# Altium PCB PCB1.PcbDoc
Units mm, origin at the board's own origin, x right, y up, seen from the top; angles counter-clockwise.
Board outline 66.42 x 67.44 mm, 2 copper layers (Top Layer, Bottom Layer); 8 components, 7 nets, 62 pads, 4 vias.
Unrouted connection lines stored in the file: 3.
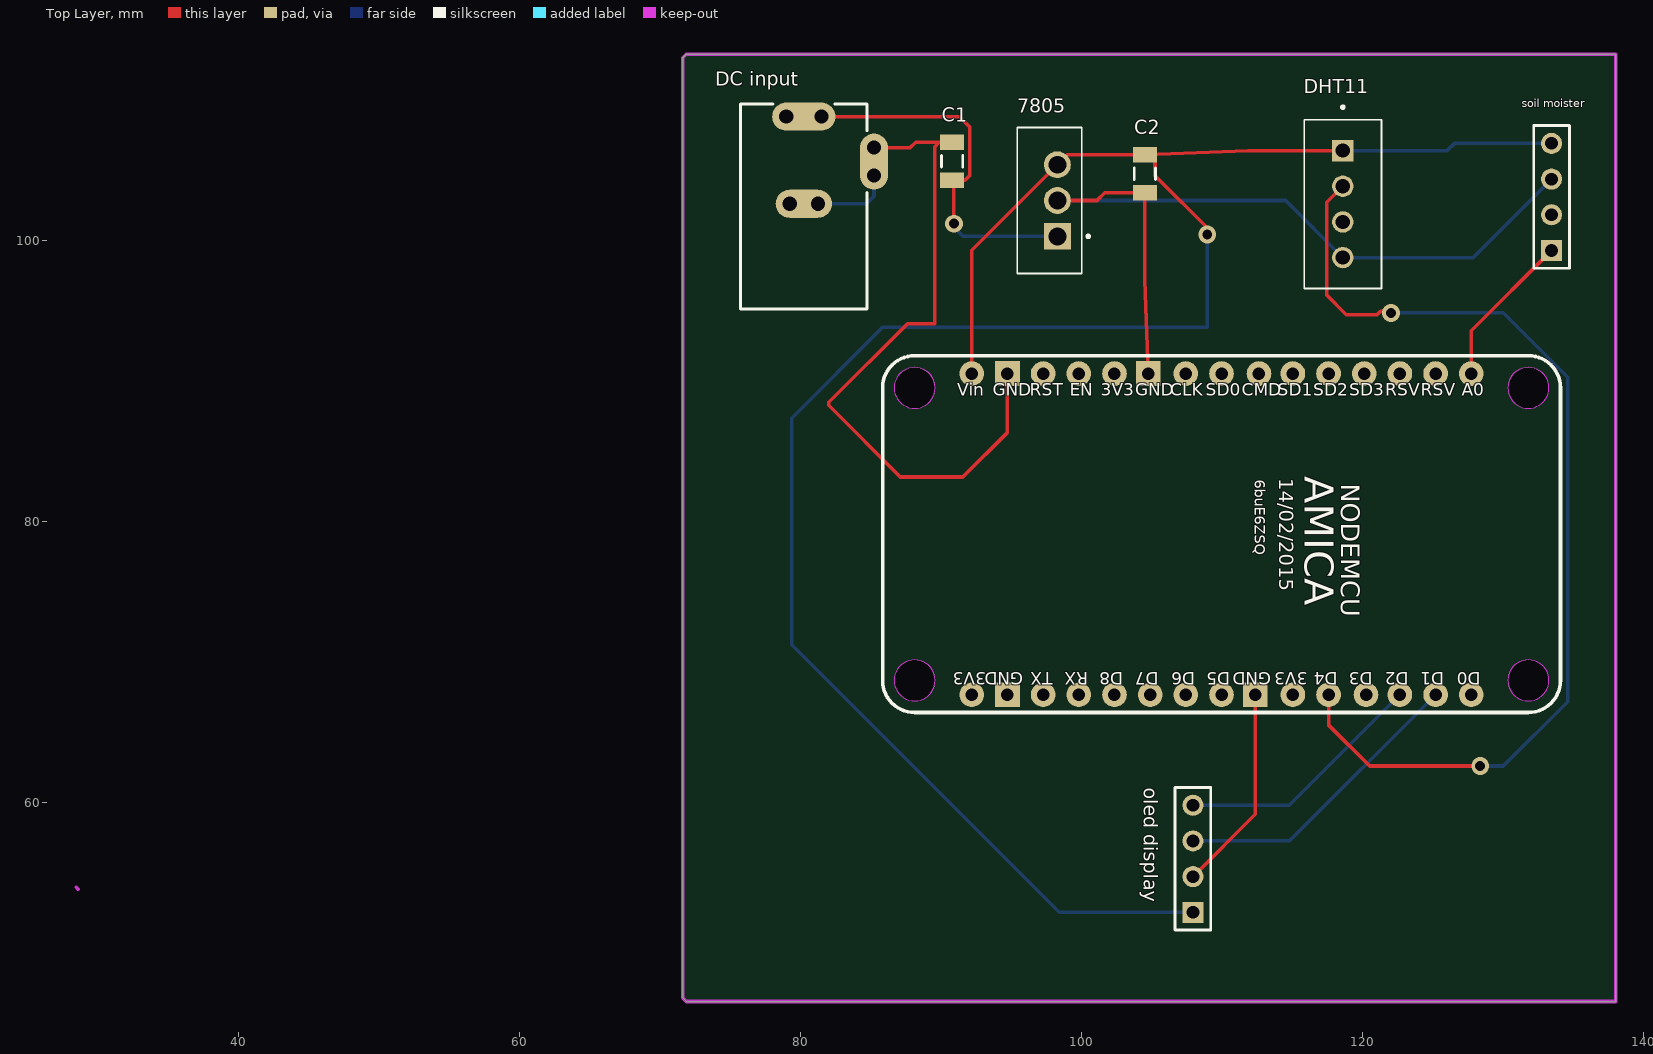
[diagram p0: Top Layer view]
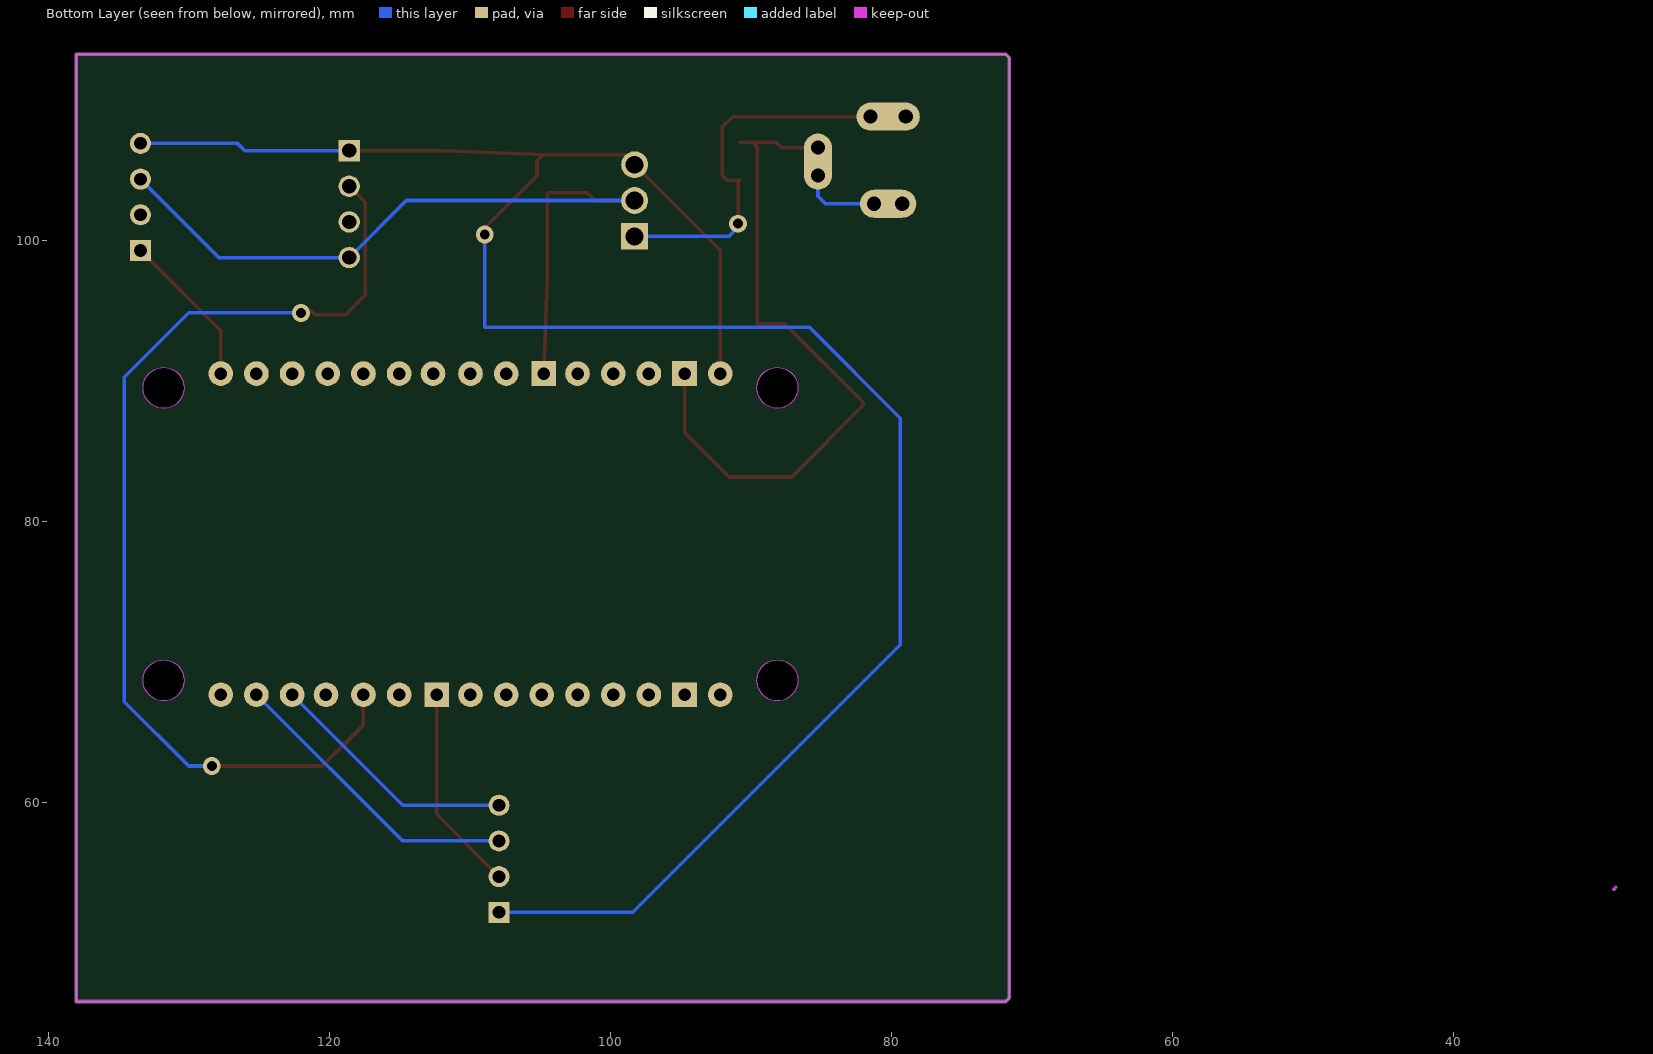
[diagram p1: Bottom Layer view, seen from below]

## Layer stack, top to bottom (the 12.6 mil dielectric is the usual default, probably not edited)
Top Solder: solder mask 0.0102, Solder Resist, Dk 3.5
Top Layer: signal copper 0.0356
Dielectric 1: dielectric 0.32, FR-4, Dk 4.8
Bottom Layer: signal copper 0.0356
Bottom Solder: solder mask 0.0102, Solder Resist, Dk 3.5

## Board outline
71.628,46.101 71.882,45.847 138.049,45.847 138.049,113.284 71.882,113.284 71.628,113.03

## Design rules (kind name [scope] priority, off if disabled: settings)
Clearance [All] p1: gap=0.254 ignorepadtopadclearanceinfootprint=FALSE except(0: Arc-Hole Track-Hole SMDPad-Hole THPad-Hole Via-Hole Fill-Hole Poly-Hole Region-Hole Text-Hole)
PolygonConnect [All] p1: connectstyle=Relief reliefconductorwidth=0.254 reliefentries=4 polygonreliefangle="90 Angle" airgapwidth=0.254
RoutingVias [All] p1: holewidth=0.711 width=1.27 viastyle="Through Hole" minholewidth=0.711 minwidth=1.27 maxholewidth=0.711 maxwidth=1.27
SolderMaskExpansion [All] p1: expansion=0.102 istentingtop=FALSE
Width [All] p1: maxlimit=0.254 minlimit=0.254 preferedwidth=0.254
30 further rules are at their usual default settings.

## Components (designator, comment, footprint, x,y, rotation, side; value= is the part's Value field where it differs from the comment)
7805 "L7805CV" TO255P1040X460X1968-3 98.298,100.32 r90 top
C1 "" C1206 90.805,105.664 r270 top value=10u
C2 "" C1206 104.521,104.775 r90 top value=0.1u
"DC input" "PWR2.5" KLD-0202 80.244,95.139 r90 top
DHT11 "ADA386" XDCR_ADA386 118.618,102.616 r270 top
NodeMCU-? "NodeMCU V1.0 ESP-12E" "NodeMCU V1.0 ESP-12E" 134.01,91.846 r270 top
"oled display" "" HDR1X4 107.95,52.197 r90 top
"soil moister" "" HDR1X4 133.477,99.314 r90 top

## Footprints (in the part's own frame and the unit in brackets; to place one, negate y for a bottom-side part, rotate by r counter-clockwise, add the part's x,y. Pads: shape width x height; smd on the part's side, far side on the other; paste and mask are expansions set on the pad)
C1206 [mm] "Chip Capacitor, Body 3.2x1.6mm, IPC High Density"
  rect 1.1x1.7 smd: 1(-1.35,0) 2(1.35,0)
  silkscreen extent -0.4,-0.75 0.4,0.75, body extent -1.7,-0.9 1.7,0.9, height 1.3
HDR1X4 [mm] "Connector; Header; 4 Position"
  rect 1.5x1.5 hole 0.9: 1(0,0)
  round 1.5 hole 0.9: 2(2.54,0) 3(5.08,0) 4(7.62,0)
  silkscreen extent -1.27,-1.27 8.89,1.27
KLD-0202 [mm] "DC Power Jack, 2.5mm, KLD Series, PCB Mount"
  oval 2x4.5 all layers, no hole: 1(13.7,0)
  round 1.5 hole 1: 1A(13.7,-1.25) 1B(13.7,1.25) 2A(7.5,-1) 2B(7.5,1) 3A(9.5,-5) 3B(11.5,-5)
  oval 2x4 all layers, no hole: 2(7.5,0)
  oval 4x2 all layers, no hole: 3(10.5,-5)
  silkscreen extent 0,-4.5 14.6,4.5
"NodeMCU V1.0 ESP-12E" [mil]
  round 115 hole 115 unplated paste-300 mask-300: 0(91,-86) 0(91,-1806) 0(911,-86) 0(911,-1806)
  round 69 hole 35: 3V3(51,-1246) 3V3(951,-746) 3V3(951,-1646) A0(51,-246) CLK(51,-1046) CMD(51,-841) D0(951,-246) D1(951,-346) D2(951,-446) D3(951,-541) D4(951,-646) D5(951,-946) D6(951,-1046) D7(951,-1146) D8(951,-1246) EN(51,-1346) RST(51,-1446) RSV(51,-346) RSV(51,-446) RX(951,-1346) SD0(51,-946) SD1(51,-746) SD2(51,-646) SD3(51,-546) TX(951,-1446) VIN(51,-1646)
  rect 69x69 hole 35: GND(51,-1151) GND(51,-1546) GND(951,-851) GND(951,-1546)
  Keep-Out Layer circle w2: c911,-1806 r57.5
  Keep-Out Layer circle w2: c91,-1806 r57.5
  Keep-Out Layer circle w2: c911,-86 r57.5
  Keep-Out Layer circle w2: c91,-86 r57.5
  silkscreen extent 1,-1896 1001,4
TO255P1040X460X1968-3 [mm]
  rect 1.91x1.91 hole 1.27: 1(0,0)
  round 1.91 hole 1.27: 2(2.55,0) 3(5.1,0)
  silkscreen extent -2.65,-2.29 7.75,2.86
XDCR_ADA386 [mil]
  rect 60x60 hole 40: 1(-150,0)
  round 60 hole 40: 2(-50,0) 3(50,0) 4(150,0)
  silkscreen extent -276,-108 236,108

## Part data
7805: "Linear Voltage Regulator IC 1 Output 1.5A TO-220AB", Package="TO-220 STMicroelectronics"
C1 C2: library part "Cap Semi", "Capacitor (Semiconductor SIM Model)"
"DC input": "Low Voltage Power Supply Connector"
DHT11: Package=None
NodeMCU-?: "NodeMCU V1.0 ESP8266 (ESP-12E)"
"oled display": library part "Header 4"
"soil moister": library part "Header 4", "soil moister pin header"

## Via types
v1: diameter 1.27, hole 0.711, Top Layer to Bottom Layer, 4 vias

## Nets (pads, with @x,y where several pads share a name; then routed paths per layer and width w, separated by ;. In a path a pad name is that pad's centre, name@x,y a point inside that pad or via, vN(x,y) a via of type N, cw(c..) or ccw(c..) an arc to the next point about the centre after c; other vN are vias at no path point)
A0: "soil moister.1" NodeMCU-?.A0 | length 11.1
  Top Layer w0.254: NodeMCU-?.A0 127.762,93.599 133.477,99.314
DATA: DHT11.2 NodeMCU-?.D4 | length 73.4
  Top Layer w0.254: NodeMCU-?.D4 117.602,65.532 120.523,62.611 v1(128.397,62.611) ; DHT11.2 117.475,102.743 117.475,96.139 118.872,94.742 121.051,94.742 121.305,94.996 121.92,94.996 v1(122.047,94.869)
  Bottom Layer w0.254: v1(122.047,94.869) 130.048,94.869 134.62,90.297 134.62,67.183 130.048,62.611 v1(128.397,62.611)
GND: 7805.2 "DC input.2" "DC input.2A" "DC input.2B" "DC input.3" "DC input.3A" "DC input.3B" "oled display.2" "soil moister.3" C1.1 C2.1 DHT11.4 NodeMCU-?.GND | length 133.2
  Top Layer w0.254: 85.244,104.639 85.244,105.639 85.244,106.639 87.833,106.639 88.208,107.014 89.894,107.014 ; C1.1 89.894,107.014 ; NodeMCU-?.GND@94.742,90.551 94.742,86.36 91.567,83.185 87.122,83.185 82.02,88.287 82.02,88.497 87.63,94.107 89.56,94.107 89.56,106.68 89.894,107.014 ; 7805.2 101.117,102.87 101.672,103.425 C2.1 104.521,97.231 NodeMCU-?.GND@104.775,90.551 ; 107.95,54.737 112.395,59.182 NodeMCU-?.GND@112.395,67.691
  Bottom Layer w0.254: 79.244,102.639 80.244,102.639 81.244,102.639 84.709,102.639 85.244,103.174 85.244,104.639 85.244,105.639 ; 7805.2 114.554,102.87 DHT11.4 127.889,98.806 133.477,104.394
Net7805_1: 7805.1 "DC input.1" "DC input.1A" "DC input.1B" C1.2 | length 30.5
  Top Layer w0.254: 80.244,108.839 81.494,108.839 91.313,108.839 92.05,108.102 92.05,104.648 91.716,104.314 C1.2 90.932,104.187 v1(90.932,101.219)
  Bottom Layer w0.254: 78.994,108.839 80.244,108.839 81.494,108.839 ; v1@90.773,101.124 91.577,100.32 7805.1
SCL: "oled display.3" NodeMCU-?.D1 | length 21.6
  Bottom Layer w0.254: 107.95,57.277 114.808,57.277 NodeMCU-?.D1
SDA: "oled display.4" NodeMCU-?.D2 | length 18
  Bottom Layer w0.254: 107.95,59.817 114.808,59.817 NodeMCU-?.D2
VCC: 7805.3 "oled display.1" "soil moister.4" C2.2 DHT11.1 NodeMCU-?.VIN | length 152.1
  Top Layer w0.254: NodeMCU-?.VIN 92.202,99.324 7805.3 99.003,106.125 C2.2 ; v1@109.176,100.708 105.244,104.641 105.244,105.702 104.821,106.125 C2.2 ; DHT11.1 111.883,106.426 C2.2
  Bottom Layer w0.254: 107.95,52.197 98.425,52.197 79.375,71.247 79.375,87.376 85.852,93.853 108.966,93.853 v1(108.966,100.457) ; DHT11.1 126.06,106.426 126.568,106.934 133.477,106.934
pads on no net: "soil moister.2" DHT11.3 NodeMCU-?.0 NodeMCU-?.3V3 NodeMCU-?.CLK NodeMCU-?.CMD NodeMCU-?.D0 NodeMCU-?.D3 NodeMCU-?.D5 NodeMCU-?.D6 NodeMCU-?.D7 NodeMCU-?.D8 NodeMCU-?.EN NodeMCU-?.RST NodeMCU-?.RSV NodeMCU-?.RX NodeMCU-?.SD0 NodeMCU-?.SD1 NodeMCU-?.SD2 NodeMCU-?.SD3 NodeMCU-?.TX

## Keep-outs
Keep-Out Layer:
  lines w0.254: 28.448,53.975 28.575,53.848 ; 71.628,46.101 71.882,45.847 138.049,45.847 138.049,112.141 138.049,113.284 71.882,113.284 71.628,113.03 71.628,46.101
